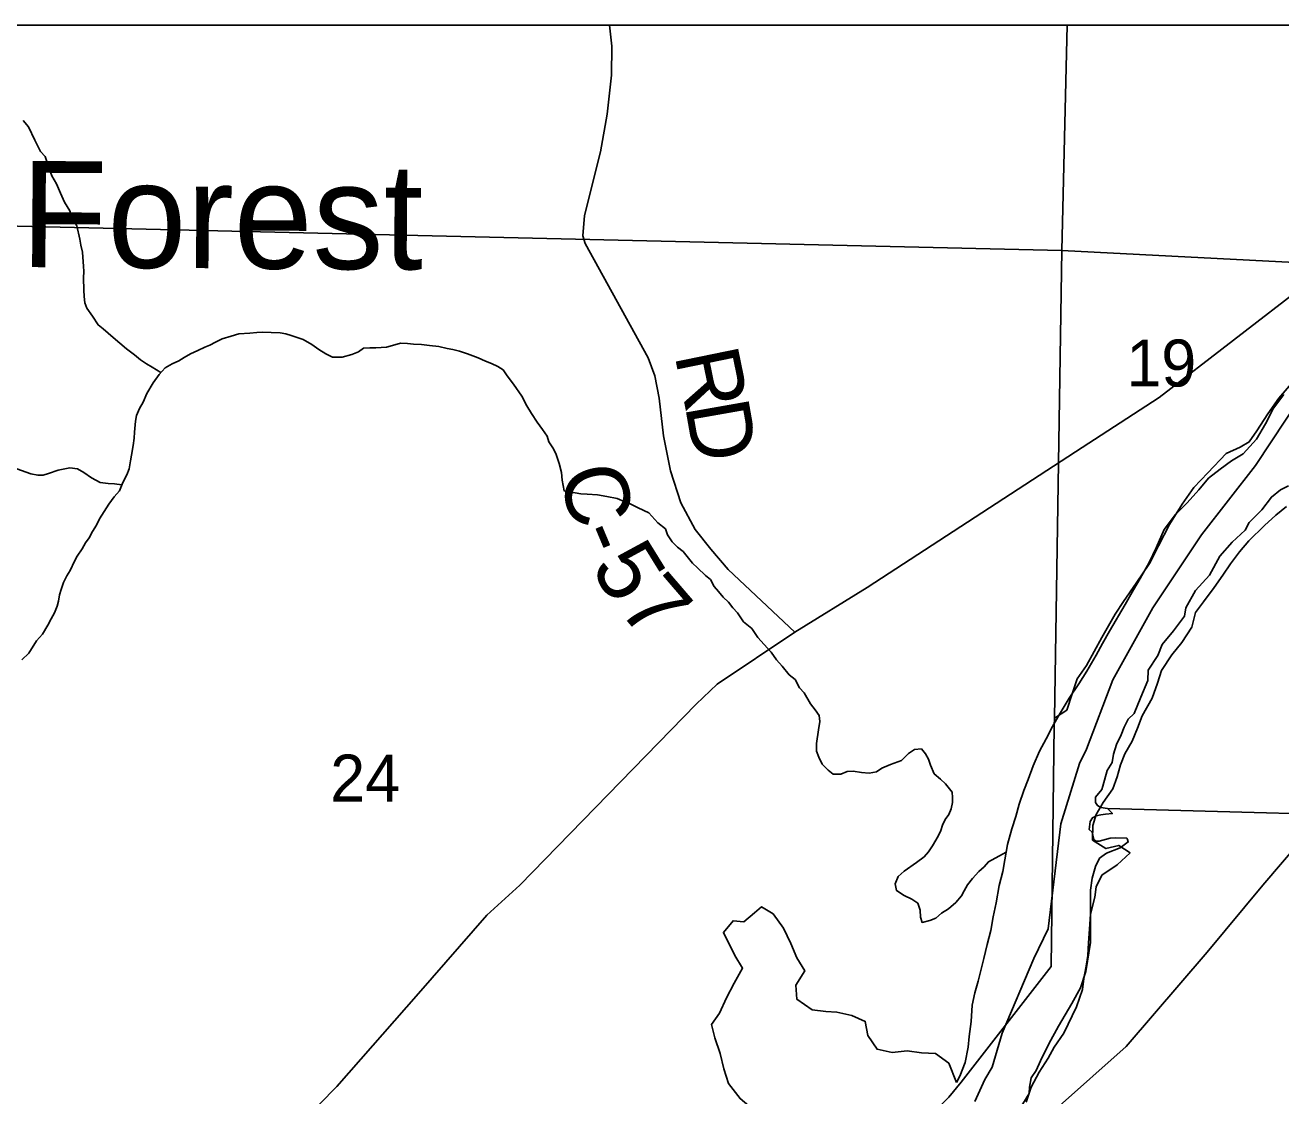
# Model space of a CAD drawing. Extents: x 0 to 34, y 0 to 22.
# Drawn here: x 3.401 to 4.521, y 19.945 to 20.9 of the extents above; entities that cross this region are included whole.
import ezdxf

# ---------------------------------------------------------------- set-up
doc = ezdxf.new("R2010")
doc.units = 0
for name, color, linetype in [('Default', 7, 'Continuous'), ('GM_X_County_Road', 7, 'Continuous'), ('GM_X_County_Road_Text', 7, 'Continuous'), ('GM_X_Major_Lake_Text', 7, 'Continuous'), ('GM_X_Major_River', 7, 'Continuous'), ('GM_X_Minor_River', 7, 'Continuous'), ('GM_X_Rail_Line', 7, 'Continuous'), ('GM_X_Section', 7, 'Continuous'), ('GM_X_Section_Text', 7, 'Continuous'), ('GM_X_State_Route', 7, 'Continuous'), ('SH_Data', 7, 'Continuous')]:
    doc.layers.add(name, color=color, linetype=linetype)

msp = doc.modelspace()

# ---------------------------------------------------------------- linework, layer by layer
at = {"layer": 'Default'}
msp.add_lwpolyline([(4.3307, 20.9), (3.1961, 20.9), (3.1645, 20.7261), (4.3261, 20.699)], close=True, dxfattribs=at)
at = {"layer": 'GM_X_County_Road'}
msp.add_lwpolyline([(4.088, 20.3587), (4.0285, 20.4143), (4.0131, 20.4326), (3.9991, 20.4501), (3.9861, 20.474), (3.9771, 20.5024), (3.9707, 20.5337), (3.9668, 20.5673), (3.9631, 20.5871), (3.9572, 20.6033), (3.9008, 20.7052), (3.8987, 20.7121), (3.9004, 20.7303), (3.9145, 20.7869), (3.9204, 20.8206), (3.9245, 20.8554), (3.9248, 20.8812), (3.9226, 20.9)], dxfattribs=at)
at = {"layer": 'GM_X_Major_River'}
for points in [[(4.5241, 20.5704), (4.5148, 20.5584), (4.5076, 20.5445), (4.4997, 20.5306), (4.4876, 20.5176), (4.4772, 20.5114), (4.4672, 20.504), (4.4568, 20.4959), (4.4482, 20.4854), (4.4377, 20.4739), (4.4275, 20.4634), (4.4174, 20.45), (4.4102, 20.4338), (4.4038, 20.4206), (4.3959, 20.4063), (4.3899, 20.3962), (4.3824, 20.3831), (4.3686, 20.3594), (4.3623, 20.3485), (4.3567, 20.338), (4.3484, 20.3238), (4.3413, 20.3125), (4.3327, 20.2998), (4.3236, 20.2848), (4.3177, 20.2743), (4.3121, 20.2634), (4.3062, 20.2525), (4.3006, 20.2393), (4.2961, 20.2272), (4.2921, 20.2174), (4.288, 20.205), (4.2851, 20.194), (4.2815, 20.183), (4.2777, 20.1691), (4.2751, 20.1554), (4.2734, 20.1452), (4.2701, 20.1327), (4.2674, 20.1172), (4.2649, 20.1047), (4.2627, 20.0926), (4.2594, 20.0801), (4.2564, 20.0676), (4.2514, 20.0472), (4.2485, 20.037), (4.246, 20.026), (4.2453, 20.0112), (4.2435, 19.998), (4.2425, 19.9885), (4.2399, 19.9748), (4.2351, 19.9624), (4.2322, 19.957)], [(4.2942, 19.9394), (4.2986, 19.9526), (4.3058, 19.9661), (4.3137, 19.9785), (4.3192, 19.9883), (4.3278, 20.001), (4.339, 20.0243), (4.3443, 20.0398), (4.3456, 20.0497), (4.3478, 20.0606), (4.3491, 20.0701), (4.3498, 20.0815), (4.3508, 20.0937), (4.3515, 20.1069), (4.3553, 20.1221), (4.3566, 20.1315), (4.3618, 20.1417), (4.3753, 20.1509), (4.3869, 20.1617), (4.3768, 20.1684), (4.3654, 20.1656), (4.3534, 20.1731), (4.3537, 20.186), (4.3566, 20.1958), (4.3629, 20.2067), (4.3715, 20.2187), (4.3755, 20.2296), (4.3784, 20.2402), (4.3821, 20.25), (4.3888, 20.2612), (4.3936, 20.2729), (4.3977, 20.2839), (4.4067, 20.2996), (4.4112, 20.3132), (4.4149, 20.3245), (4.424, 20.3384), (4.4329, 20.3492), (4.442, 20.3631), (4.4453, 20.376), (4.4524, 20.3857), (4.4618, 20.3984), (4.4696, 20.4093), (4.4763, 20.4194), (4.4845, 20.4302), (4.4927, 20.4399), (4.5067, 20.4537), (4.5168, 20.463), (4.5264, 20.4707)], [(4.2322, 19.957), (4.2251, 19.974), (4.2135, 19.9827), (4.201, 19.9833), (4.1881, 19.9851), (4.1748, 19.9835), (4.1612, 19.9865), (4.1531, 19.9988), (4.1507, 20.0114), (4.1387, 20.0167), (4.1255, 20.0196), (4.1156, 20.0202), (4.1035, 20.0216), (4.0897, 20.0311), (4.0888, 20.0436), (4.0967, 20.0564), (4.0897, 20.068), (4.0843, 20.081), (4.0778, 20.0945), (4.0686, 20.1072), (4.0581, 20.1135), (4.052, 20.1082)], [(4.052, 20.1082), (4.0423, 20.1002), (4.0328, 20.1012), (4.0242, 20.0907), (4.0344, 20.0703), (4.0413, 20.0588), (4.0338, 20.0456), (4.027, 20.0325), (4.0207, 20.0186), (4.0136, 20.0085), (4.0167, 19.9966), (4.0214, 19.9828), (4.0245, 19.969), (4.0287, 19.956), (4.0391, 19.9425), (4.0508, 19.9329)]]:
    msp.add_lwpolyline(points, dxfattribs=at)
at = {"layer": 'GM_X_Minor_River'}
for points in [[(3.5225, 20.5901), (3.5149, 20.5949), (3.5097, 20.598), (3.5044, 20.6015), (3.4991, 20.6058), (3.492, 20.6112), (3.48, 20.6213), (3.471, 20.6291), (3.4665, 20.6326), (3.4617, 20.6403), (3.4565, 20.6476), (3.4547, 20.6522), (3.454, 20.658), (3.4538, 20.6637), (3.4536, 20.6747), (3.4537, 20.6801), (3.4534, 20.685), (3.4528, 20.693), (3.4525, 20.6976), (3.4511, 20.7037), (3.4504, 20.7091), (3.4476, 20.7209), (3.4428, 20.7286), (3.4413, 20.7344), (3.4365, 20.742), (3.4329, 20.7501), (3.4296, 20.7585), (3.4252, 20.7655), (3.4226, 20.7731), (3.4194, 20.7827), (3.4153, 20.7873), (3.4101, 20.7973), (3.4046, 20.8092), (3.3998, 20.815)], [(3.897, 20.482), (3.892, 20.4829), (3.8867, 20.4833), (3.8822, 20.4845), (3.8805, 20.4941), (3.8798, 20.501), (3.8777, 20.509), (3.8752, 20.517), (3.8726, 20.522), (3.8685, 20.5282), (3.8671, 20.5335), (3.863, 20.5393), (3.8582, 20.5459), (3.853, 20.5536), (3.8489, 20.5605), (3.8445, 20.569), (3.8371, 20.5797), (3.8315, 20.5871), (3.8278, 20.5925), (3.8229, 20.5956), (3.8173, 20.5983), (3.812, 20.6003), (3.8055, 20.6031), (3.8006, 20.6051), (3.7961, 20.6067), (3.7889, 20.6091), (3.7828, 20.6107), (3.7779, 20.6116), (3.7703, 20.6132), (3.762, 20.6141), (3.7551, 20.615), (3.7479, 20.6155), (3.7426, 20.6159), (3.7361, 20.6164), (3.7292, 20.6143), (3.7239, 20.6128), (3.7143, 20.6122), (3.709, 20.6123), (3.7033, 20.612), (3.6987, 20.6087), (3.6929, 20.6061), (3.6841, 20.6039), (3.6757, 20.6037), (3.6697, 20.6068), (3.6633, 20.6108), (3.6573, 20.615), (3.6494, 20.6197), (3.6388, 20.6233), (3.6339, 20.6246), (3.6289, 20.6254), (3.621, 20.6259), (3.613, 20.626), (3.608, 20.6257), (3.6019, 20.6251), (3.592, 20.6245), (3.5851, 20.6227), (3.5771, 20.6202), (3.5713, 20.6172), (3.5663, 20.6146), (3.5617, 20.6128), (3.5556, 20.6098), (3.549, 20.6069), (3.5433, 20.6036), (3.5386, 20.6006), (3.5325, 20.598), (3.5263, 20.5943), (3.5209, 20.5883), (3.5158, 20.5808), (3.5099, 20.5713), (3.5068, 20.5638), (3.5036, 20.5581), (3.5008, 20.5517), (3.5, 20.5467), (3.499, 20.5368), (3.4986, 20.5315), (3.4977, 20.5251), (3.4964, 20.5163), (3.4955, 20.5114), (3.4943, 20.5042), (3.4923, 20.4989), (3.4887, 20.4921), (3.4855, 20.4845), (3.4809, 20.4792), (3.4762, 20.4728), (3.4679, 20.4596), (3.4652, 20.454), (3.4616, 20.4483), (3.4585, 20.4427), (3.4554, 20.4381), (3.4522, 20.4328), (3.4479, 20.4264), (3.4455, 20.4219), (3.4416, 20.4136), (3.4388, 20.4087), (3.4357, 20.403), (3.4337, 20.3966), (3.4321, 20.392), (3.4312, 20.3863), (3.43, 20.3818), (3.4276, 20.3757), (3.4248, 20.3704)], [(3.4878, 20.49), (3.4811, 20.491), (3.4754, 20.4911), (3.4685, 20.492), (3.4606, 20.4963), (3.4538, 20.501), (3.4482, 20.5042), (3.4414, 20.505), (3.431, 20.5029), (3.4222, 20.5), (3.4176, 20.4986), (3.4127, 20.4986), (3.4066, 20.4999), (3.3941, 20.5043)], [(4.2765, 20.1624), (4.2606, 20.1538), (4.2567, 20.1493), (4.2521, 20.1452), (4.2463, 20.1388), (4.242, 20.1332), (4.2388, 20.1279), (4.2365, 20.1234), (4.2314, 20.1174), (4.2248, 20.1118), (4.2187, 20.108), (4.2137, 20.1036), (4.2083, 20.1014), (4.2014, 20.0996), (4.2, 20.1045), (4.1997, 20.1106), (4.1975, 20.1168), (4.1923, 20.1203), (4.1855, 20.1238), (4.1787, 20.1281), (4.1773, 20.1342), (4.1801, 20.1407), (4.1855, 20.1455), (4.1963, 20.153), (4.2032, 20.1582), (4.2071, 20.1627), (4.2106, 20.168), (4.2157, 20.1767), (4.2181, 20.1816), (4.2197, 20.1865), (4.2221, 20.1914), (4.2252, 20.1959), (4.2272, 20.2009), (4.2285, 20.2066), (4.2286, 20.2111), (4.2283, 20.2157), (4.2223, 20.2234), (4.2178, 20.2273), (4.2122, 20.2323), (4.2089, 20.24), (4.2071, 20.2454), (4.2045, 20.25), (4.2008, 20.2546), (4.1947, 20.254), (4.1893, 20.2502), (4.1831, 20.2442), (4.1731, 20.2406), (4.1655, 20.2373), (4.1608, 20.2339), (4.1543, 20.2329), (4.1475, 20.2334), (4.1399, 20.2347), (4.1346, 20.2344), (4.1288, 20.2318), (4.122, 20.2319), (4.1175, 20.2354), (4.1122, 20.2408), (4.1093, 20.247), (4.1071, 20.2523), (4.1072, 20.2592), (4.109, 20.2713), (4.1103, 20.2789), (4.1096, 20.2843), (4.1059, 20.2893), (4.1018, 20.2947), (4.0963, 20.3043), (4.0922, 20.3089), (4.0881, 20.3163), (4.0829, 20.3205), (4.0765, 20.3282), (4.0717, 20.334), (4.0668, 20.3406), (4.0605, 20.3476), (4.0549, 20.3537), (4.0497, 20.3618), (4.0422, 20.3677), (4.0367, 20.3758), (4.0326, 20.3804), (4.0288, 20.3854), (4.024, 20.3897), (4.0199, 20.3947), (4.0161, 20.3993), (4.0128, 20.4055), (4.0083, 20.409), (4.0012, 20.4159), (3.9967, 20.4202), (3.9882, 20.4306), (3.9833, 20.4345), (3.9784, 20.4392), (3.9744, 20.4453), (3.9725, 20.4507), (3.9658, 20.4561), (3.9576, 20.465), (3.9481, 20.4694), (3.941, 20.4729), (3.9364, 20.4749), (3.9296, 20.4777), (3.9202, 20.4797), (3.9118, 20.481), (3.9027, 20.4815), (3.897, 20.482)], [(3.4248, 20.3704), (3.4217, 20.3648), (3.417, 20.3569), (3.4115, 20.3508), (3.4048, 20.3399), (3.3986, 20.3339)]]:
    msp.add_lwpolyline(points, dxfattribs=at)
at = {"layer": 'GM_X_Rail_Line'}
msp.add_lwpolyline([(4.0971, 19.3526), (4.0971, 19.4175), (4.1034, 19.4841), (4.1353, 19.5729), (4.219, 19.7566), (4.2492, 19.8256), (4.2772, 19.8815), (4.3213, 19.9337), (4.3834, 19.9889), (4.4557, 20.0732), (4.5053, 20.133), (4.6016, 20.2455), (4.6862, 20.3389), (4.7356, 20.3882), (4.8861, 20.5288), (4.9518, 20.5917), (4.997, 20.6442), (5.022, 20.6941), (5.048, 20.7585), (5.0622, 20.8479), (5.0705, 20.9)], dxfattribs=at)
at = {"layer": 'GM_X_Section'}
msp.add_lwpolyline([(3.1645, 20.7261), (4.3261, 20.699), (4.3194, 20.2817), (4.3193, 20.2753), (4.3164, 20.0605), (4.2362, 19.9572), (4.2253, 19.9438), (4.2171, 19.9357), (4.2598, 19.9346), (4.2313, 19.8855), (4.2007, 19.856), (4.1813, 19.8371), (4.1568, 19.8116), (4.1378, 19.745), (3.0048, 19.785)], close=True, dxfattribs=at)
for points in [[(4.5344, 20.5845), (4.5196, 20.5674), (4.5098, 20.5533), (4.4999, 20.538), (4.4932, 20.5283), (4.4852, 20.5236), (4.4725, 20.5178), (4.4562, 20.5008), (4.4438, 20.4875), (4.4332, 20.4726), (4.4221, 20.4546), (4.4122, 20.4356), (4.4042, 20.4198), (4.3924, 20.4023), (4.3811, 20.3859), (4.3736, 20.3747), (4.3617, 20.3538), (4.3479, 20.3288), (4.3396, 20.3168), (4.3351, 20.3037), (4.3306, 20.289), (4.3194, 20.2817), (4.3261, 20.699), (4.6319, 20.6833)], [(4.6719, 20.1929), (4.3667, 20.2014), (4.3607, 20.2023), (4.3577, 20.2039), (4.3559, 20.2066), (4.356, 20.2115), (4.3618, 20.2182), (4.3627, 20.2212), (4.3664, 20.2351), (4.3708, 20.2422), (4.3721, 20.2498), (4.3749, 20.2584), (4.3789, 20.267), (4.3817, 20.2738), (4.3853, 20.2809), (4.3904, 20.2861), (4.3964, 20.3007), (4.4028, 20.3153), (4.4031, 20.3248), (4.4117, 20.3378), (4.4154, 20.3476), (4.4255, 20.3598), (4.4353, 20.3729), (4.4366, 20.3804), (4.4453, 20.3957), (4.4578, 20.4094), (4.4669, 20.4263), (4.4778, 20.4389), (4.4894, 20.4496), (4.493, 20.4563), (4.5043, 20.4678), (4.5129, 20.479), (4.521, 20.4856), (4.5283, 20.4892)], [(4.289, 19.9339), (4.2969, 19.947), (4.2971, 19.9527), (4.2988, 19.961), (4.3031, 19.9677), (4.3071, 19.9763), (4.3143, 19.9913), (4.323, 20.007), (4.3349, 20.0275), (4.3428, 20.0413), (4.3473, 20.056), (4.3517, 20.0817), (4.3517, 20.1283), (4.3531, 20.1392), (4.356, 20.1494), (4.3596, 20.1569), (4.3658, 20.1613), (4.378, 20.1663), (4.3853, 20.1714), (4.3846, 20.1737), (4.3839, 20.1748), (4.3741, 20.1751), (4.3691, 20.1748), (4.3592, 20.172), (4.3562, 20.1721), (4.3547, 20.1737), (4.353, 20.1801), (4.3504, 20.1825), (4.3513, 20.1896), (4.3533, 20.193), (4.3567, 20.1948), (4.3609, 20.1955), (4.3651, 20.1961), (4.3712, 20.1967), (4.3667, 20.2014), (4.6719, 20.1929)]]:
    msp.add_lwpolyline(points, dxfattribs=at)
at = {"layer": 'GM_X_State_Route'}
for points in [[(3.6332, 19.9061), (3.6794, 19.9534), (3.7523, 20.0363), (3.8132, 20.1061), (3.8426, 20.1329), (4, 20.2944), (4.0187, 20.3121), (4.088, 20.3587), (4.1525, 20.3983), (4.3383, 20.5193), (4.4127, 20.568), (4.5454, 20.6702), (4.7265, 20.8124), (4.8353, 20.9)], [(4.5394, 20.5687), (4.4986, 20.5071), (4.4507, 20.4453), (4.4072, 20.3803), (4.3714, 20.3159), (4.3481, 20.2542), (4.3417, 20.2414), (4.3251, 20.1876), (4.3139, 20.094), (4.3011, 20.0674), (4.2727, 20.0009), (4.264, 19.9705), (4.2573, 19.9596), (4.2485, 19.94)]]:
    msp.add_lwpolyline(points, dxfattribs=at)
at = {"layer": 'SH_Data'}
msp.add_line((2.1, 20.9), (8.9, 20.9), dxfattribs=at)

# ---------------------------------------------------------------- texts
at = {"layer": 'GM_X_County_Road_Text'}
for s, rotation, p in [('R', 281.5696, (3.9805, 20.606)), ('D', 280.0058, (3.9898, 20.5607)), ('C', 283.6065, (3.8775, 20.5014)), ('-', 292.7159, (3.8916, 20.4467)), ('5', 301.7465, (3.9051, 20.4165)), ('7', 310.7166, (3.9292, 20.3789))]:
    msp.add_text(s, height=0.0568, rotation=rotation, dxfattribs=at).set_placement(p)
at = {"layer": 'GM_X_Major_Lake_Text'}
msp.add_text('Forest', height=0.09469, rotation=359.6558, dxfattribs=at).set_placement((3.3973, 20.6842))
at = {"layer": 'GM_X_Section_Text'}
for s, p in [('19', (4.3836, 20.5777)), ('24', (3.6736, 20.2075))]:
    msp.add_text(s, height=0.04186, rotation=0, dxfattribs=at).set_placement(p)

doc.saveas('drawing.dxf')
